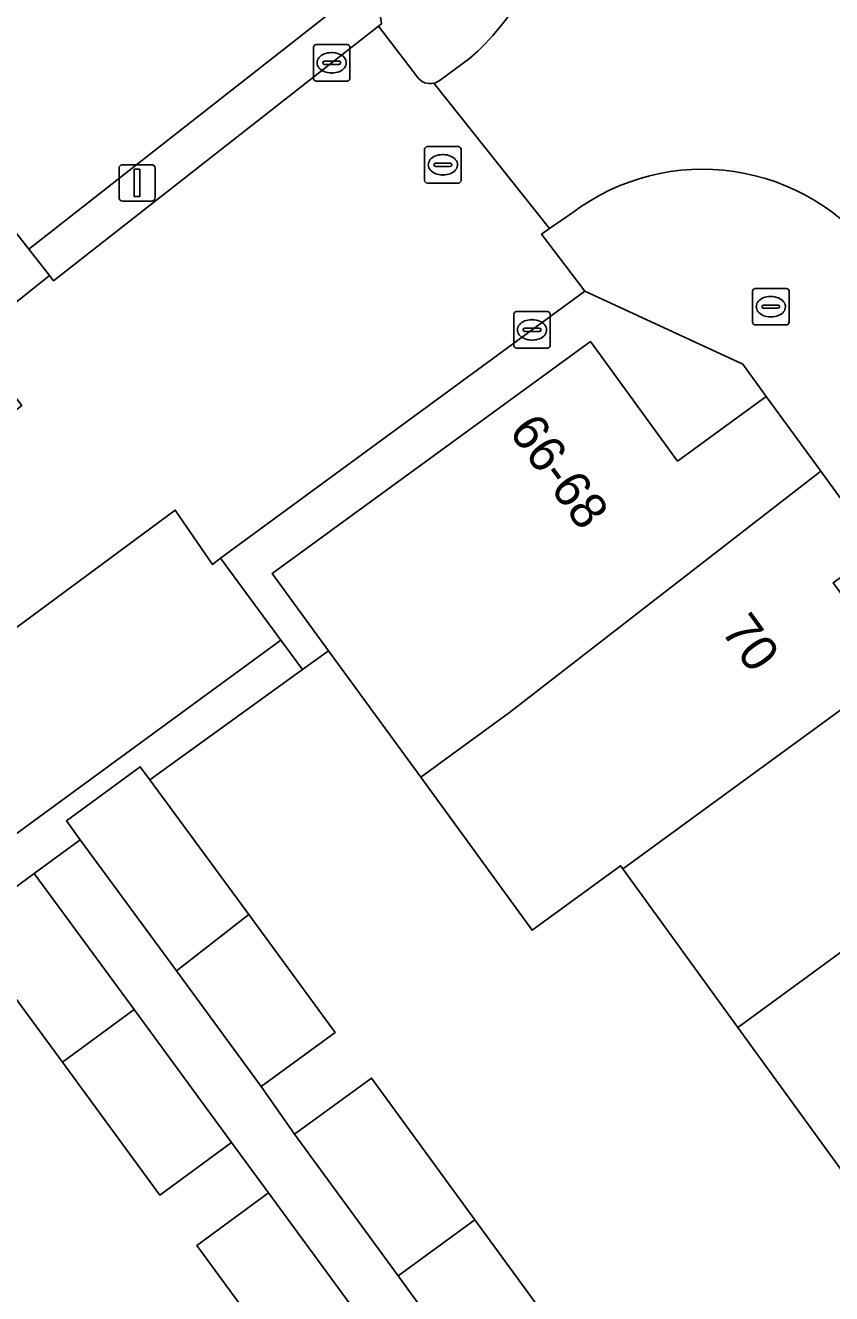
# Model space of a CAD drawing. Extents: x 160377 to 161131, y 383938 to 384853.
# Drawn here: x 160774.47 to 160796.6, y 384297.65 to 384332.45 of the extents above; entities that cross this region are included whole.
import ezdxf

# ---------------------------------------------------------------- set-up
doc = ezdxf.new("R2010")
doc.units = 0
for name, color, linetype in [('IMGEO_Brandkraan', 7, 'Continuous'), ('IMGEO_Erf', 7, 'Continuous'), ('IMGEO_Kolk', 7, 'Continuous'), ('IMGEO_Lichtmast', 7, 'Continuous'), ('IMGEO_Muur', 7, 'Continuous'), ('IMGEO_Pand', 7, 'Continuous'), ('IMGEO_Pand_nummerreeks', 7, 'Continuous'), ('IMGEO_Parkeervlak_open', 7, 'Continuous'), ('IMGEO_Rijbaan_lokaal_open', 7, 'Continuous'), ('IMGEO_Rioolput', 7, 'Continuous'), ('IMGEO_Voetpad_open', 7, 'Continuous')]:
    doc.layers.add(name, color=color, linetype=linetype)

msp = doc.modelspace()

# ---------------------------------------------------------------- linework, layer by layer
at = {"layer": 'IMGEO_Brandkraan'}
for p, q in [((160794.429, 384324.3), (160794.429, 384325.152)), ((160794.504, 384325.226), (160795.356, 384325.226)), ((160795.43, 384325.152), (160795.43, 384324.3)), ((160794.731, 384324.769), (160795.129, 384324.769)), ((160794.917, 384325.006), (160794.942, 384325.006)), ((160794.688, 384324.72), (160794.688, 384324.732)), ((160795.126, 384324.683), (160794.728, 384324.683)), ((160794.94, 384324.446), (160794.915, 384324.446)), ((160795.172, 384324.732), (160795.172, 384324.72)), ((160795.356, 384324.226), (160794.504, 384324.226))]:
    msp.add_line(p, q, dxfattribs=at)
for points in [[(160794.429, 384324.3), (160794.429, 384325.152)], [(160794.504, 384325.226), (160795.356, 384325.226)], [(160795.43, 384325.152), (160795.43, 384324.3)], [(160795.356, 384324.226), (160794.504, 384324.226)]]:
    msp.add_lwpolyline(points, dxfattribs=at)
for centre, radius, start, end in [((160794.506, 384325.15), 0.0765, 91.552, 178.448), ((160794.506, 384325.15), 0.0765, 91.552, 178.448), ((160795.354, 384325.15), 0.0765, 1.552, 88.448), ((160795.354, 384325.15), 0.0765, 1.552, 88.448), ((160794.728, 384324.729), 0.0403, 85.8775, 175.7526), ((160795.133, 384324.731), 0.0386, 1.7309, 96.639), ((160794.725, 384324.719), 0.0366, 178.938, 274.7102), ((160795.129, 384324.726), 0.043, 264.8664, 352.4533), ((160794.506, 384324.302), 0.0765, 181.552, 268.448), ((160794.506, 384324.302), 0.0765, 181.552, 268.448), ((160795.354, 384324.302), 0.0765, 271.552, 358.448), ((160795.354, 384324.302), 0.0765, 271.552, 358.448)]:
    msp.add_arc(centre, radius, start, end, dxfattribs=at)
for centre, major_axis, ratio, start_param, end_param in [((160794.916, 384324.726), (-0.387, 0.002), 0.722429, 4.712389, 7.853982), ((160794.941, 384324.726), (-0.39, 0.002), 0.717154, 1.570796, 4.712389)]:
    msp.add_ellipse(centre, major_axis=major_axis, ratio=ratio, start_param=start_param, end_param=end_param, dxfattribs=at)
at = {"layer": 'IMGEO_Erf'}
for points in [[(160784.161, 384332.424), (160784.24, 384332.486), (160783.548, 384337.293), (160782.871, 384338.156), (160780.522, 384336.316), (160783.117, 384333.004), (160774.566, 384326.307), (160775.131, 384325.585), (160775.244, 384325.441)], [(160781.247, 384317.41), (160789.979, 384323.771), (160792.369, 384320.491), (160794.806, 384322.267), (160794.159, 384323.148), (160789.826, 384325.15), (160779.821, 384317.833), (160781.485, 384315.578), (160782.079, 384314.774), (160782.792, 384315.29)]]:
    msp.add_lwpolyline(points, close=True, dxfattribs=at)
for points in [[(160797.184, 384300.607), (160794.027, 384304.956), (160790.871, 384309.304), (160790.808, 384309.391), (160788.379, 384307.622), (160785.321, 384311.819), (160782.792, 384315.29), (160782.079, 384314.774), (160777.889, 384311.744), (160780.6, 384308.05), (160782.97, 384304.821), (160780.944, 384303.335), (160781.86, 384302.027), (160783.971, 384303.568), (160786.807, 384299.682), (160789.387, 384296.147), (160787.276, 384294.606), (160788.245, 384293.386), (160790.217, 384294.857), (160793.111, 384290.977), (160795.57, 384287.68), (160793.597, 384286.209), (160794.747, 384284.594), (160796.653, 384285.998)], [(160781.693, 384295.545), (160779.177, 384298.972), (160781.143, 384300.415), (160780.127, 384301.799), (160778.161, 384300.357), (160775.484, 384304.001), (160773.157, 384307.171), (160764.092, 384300.584), (160766.451, 384297.369)]]:
    msp.add_lwpolyline(points, dxfattribs=at)
at = {"layer": 'IMGEO_Kolk'}
for p, q in [((160782.376, 384330.992), (160782.376, 384331.844)), ((160782.451, 384331.918), (160783.303, 384331.918)), ((160783.377, 384331.844), (160783.377, 384330.992)), ((160782.635, 384331.412), (160782.635, 384331.424)), ((160782.678, 384331.461), (160783.076, 384331.461)), ((160782.864, 384331.698), (160782.889, 384331.698)), ((160783.119, 384331.424), (160783.119, 384331.412)), ((160783.073, 384331.375), (160782.675, 384331.375)), ((160782.887, 384331.138), (160782.862, 384331.138)), ((160783.303, 384330.918), (160782.451, 384330.918)), ((160787.875, 384323.666), (160787.875, 384324.518)), ((160787.95, 384324.592), (160788.802, 384324.592)), ((160788.876, 384324.518), (160788.876, 384323.666)), ((160788.134, 384324.086), (160788.134, 384324.098)), ((160788.177, 384324.135), (160788.575, 384324.135)), ((160788.363, 384324.372), (160788.388, 384324.372)), ((160788.618, 384324.098), (160788.618, 384324.086)), ((160788.572, 384324.049), (160788.174, 384324.049)), ((160788.386, 384323.812), (160788.361, 384323.812)), ((160788.802, 384323.592), (160787.95, 384323.592))]:
    msp.add_line(p, q, dxfattribs=at)
for points in [[(160782.376, 384330.992), (160782.376, 384331.844)], [(160782.451, 384331.918), (160783.303, 384331.918)], [(160783.377, 384331.844), (160783.377, 384330.992)], [(160783.303, 384330.918), (160782.451, 384330.918)], [(160787.875, 384323.666), (160787.875, 384324.518)], [(160787.95, 384324.592), (160788.802, 384324.592)], [(160788.876, 384324.518), (160788.876, 384323.666)], [(160788.802, 384323.592), (160787.95, 384323.592)]]:
    msp.add_lwpolyline(points, dxfattribs=at)
for centre, radius, start, end in [((160782.453, 384331.842), 0.0765, 91.552, 178.448), ((160782.453, 384331.842), 0.0765, 91.552, 178.448), ((160783.301, 384331.842), 0.0765, 1.552, 88.448), ((160783.301, 384331.842), 0.0765, 1.552, 88.448), ((160782.675, 384331.421), 0.0403, 85.8775, 175.7526), ((160782.672, 384331.411), 0.0366, 178.938, 274.7102), ((160783.076, 384331.418), 0.043, 264.8664, 352.4533), ((160783.08, 384331.423), 0.0386, 1.7309, 96.639), ((160782.453, 384330.994), 0.0765, 181.552, 268.448), ((160782.453, 384330.994), 0.0765, 181.552, 268.448), ((160783.301, 384330.994), 0.0765, 271.552, 358.448), ((160783.301, 384330.994), 0.0765, 271.552, 358.448), ((160787.952, 384324.516), 0.0765, 91.552, 178.448), ((160787.952, 384324.516), 0.0765, 91.552, 178.448), ((160788.8, 384324.516), 0.0765, 1.552, 88.448), ((160788.8, 384324.516), 0.0765, 1.552, 88.448), ((160788.174, 384324.095), 0.0403, 85.8775, 175.7526), ((160788.171, 384324.085), 0.0366, 178.938, 274.7102), ((160788.575, 384324.092), 0.043, 264.8664, 352.4533), ((160788.579, 384324.097), 0.0386, 1.7309, 96.639), ((160787.952, 384323.668), 0.0765, 181.552, 268.448), ((160787.952, 384323.668), 0.0765, 181.552, 268.448), ((160788.8, 384323.668), 0.0765, 271.552, 358.448), ((160788.8, 384323.668), 0.0765, 271.552, 358.448)]:
    msp.add_arc(centre, radius, start, end, dxfattribs=at)
for centre, major_axis, ratio, start_param, end_param in [((160782.863, 384331.418), (-0.387, 0.002), 0.722429, 4.712389, 7.853982), ((160782.888, 384331.418), (-0.39, 0.002), 0.717154, 1.570796, 4.712389), ((160788.362, 384324.092), (-0.387, 0.002), 0.722429, 4.712389, 7.853982), ((160788.387, 384324.092), (-0.39, 0.002), 0.717154, 1.570796, 4.712389)]:
    msp.add_ellipse(centre, major_axis=major_axis, ratio=ratio, start_param=start_param, end_param=end_param, dxfattribs=at)
at = {"layer": 'IMGEO_Lichtmast'}
for p, q in [((160777.139, 384328.623), (160777.929, 384328.623)), ((160777.929, 384328.623), (160777.139, 384328.623)), ((160777.039, 384327.723), (160777.039, 384328.523)), ((160777.039, 384328.523), (160777.039, 384327.723)), ((160778.029, 384328.523), (160778.029, 384327.723)), ((160778.029, 384327.723), (160778.029, 384328.523)), ((160777.929, 384327.623), (160777.139, 384327.623)), ((160777.139, 384327.623), (160777.929, 384327.623))]:
    msp.add_line(p, q, dxfattribs=at)
msp.add_lwpolyline([(160777.459, 384328.498), (160777.609, 384328.498), (160777.609, 384327.748), (160777.459, 384327.748), (160777.459, 384328.498)], dxfattribs=at)
for centre, start, end in [((160777.139, 384328.523), 90, 180), ((160777.139, 384328.523), 90, 180), ((160777.929, 384328.523), 0, 90), ((160777.929, 384328.523), 360, 90), ((160777.139, 384327.723), 180, 270), ((160777.139, 384327.723), 180, 270), ((160777.929, 384327.723), 270, 0), ((160777.929, 384327.723), 270, 0)]:
    msp.add_arc(centre, 0.1, start, end, dxfattribs=at)
at = {"layer": 'IMGEO_Muur'}
for points in [[(160782.079, 384314.774), (160782.792, 384315.29)], [(160777.889, 384311.744), (160782.079, 384314.774)]]:
    msp.add_lwpolyline(points, dxfattribs=at)
at = {"layer": 'IMGEO_Pand'}
for points in [[(160780.522, 384336.316), (160782.871, 384338.156), (160781.263, 384340.208), (160772.644, 384333.455), (160770.365, 384331.67), (160772.875, 384328.466), (160774.566, 384326.307), (160783.117, 384333.004)], [(160796.302, 384320.213), (160794.806, 384322.267), (160792.369, 384320.491), (160789.979, 384323.771), (160781.247, 384317.41), (160782.792, 384315.29), (160785.321, 384311.819), (160787.757, 384313.594)], [(160798.376, 384314.787), (160796.645, 384317.157), (160797.875, 384318.053), (160796.302, 384320.213), (160787.757, 384313.594), (160785.321, 384311.819), (160788.379, 384307.622), (160790.808, 384309.391), (160790.871, 384309.304), (160790.959, 384309.368)], [(160794.027, 384304.956), (160794.125, 384305.027), (160801.545, 384310.447), (160798.376, 384314.787), (160790.959, 384309.368), (160790.871, 384309.304)], [(160778.613, 384306.511), (160780.6, 384308.05), (160777.889, 384311.744), (160777.622, 384312.108), (160775.596, 384310.622), (160775.975, 384310.105)], [(160794.027, 384304.956), (160797.184, 384300.607), (160797.291, 384300.685), (160804.715, 384306.108), (160801.545, 384310.447), (160794.125, 384305.027)], [(160774.715, 384309.175), (160772.747, 384307.73), (160773.157, 384307.171), (160775.484, 384304.001), (160777.452, 384305.445)], [(160778.613, 384306.511), (160780.944, 384303.335), (160782.97, 384304.821), (160780.6, 384308.05)], [(160777.452, 384305.445), (160775.484, 384304.001), (160778.161, 384300.357), (160780.127, 384301.799)], [(160784.697, 384298.14), (160786.807, 384299.682), (160783.971, 384303.568), (160781.86, 384302.027)], [(160781.143, 384300.415), (160779.177, 384298.972), (160781.693, 384295.545), (160783.658, 384296.988)], [(160784.697, 384298.14), (160787.276, 384294.606), (160789.387, 384296.147), (160786.807, 384299.682)]]:
    msp.add_lwpolyline(points, close=True, dxfattribs=at)
at = {"layer": 'IMGEO_Parkeervlak_open'}
msp.add_lwpolyline([(160761.293, 384306.371), (160763.903, 384302.735), (160781.485, 384315.578), (160779.821, 384317.833), (160779.604, 384317.657), (160778.583, 384319.147)], close=True, dxfattribs=at)
at = {"layer": 'IMGEO_Rijbaan_lokaal_open'}
for points in [[(160785.23, 384331.026), (160784.161, 384332.424), (160775.244, 384325.441), (160775.131, 384325.585), (160772.957, 384323.85), (160774.371, 384322.018), (160765.649, 384315.071), (160763.307, 384313.206), (160761.275, 384315.785), (160741.768, 384300.44), (160742.088, 384300.038), (160734.254, 384295.2)], [(160786.656, 384331.534), (160785.852, 384330.945)], [(160760.382, 384305.698), (160761.293, 384306.371), (160778.583, 384319.147), (160779.604, 384317.657), (160779.821, 384317.833), (160789.826, 384325.15), (160788.635, 384326.714), (160788.858, 384326.869), (160785.679, 384330.858)], [(160785.679, 384330.858), (160788.858, 384326.869), (160789.495, 384327.313)]]:
    msp.add_lwpolyline(points, dxfattribs=at)
for centre, radius, start, end in [((160782.686, 384336.248), 6.163, 310.1054, 36.8104), ((160785.578, 384331.271), 0.425, 215.1624, 283.8094), ((160785.59, 384331.25), 0.401, 282.74, 310.6548), ((160793.058, 384322.555), 5.944, 36.4417, 126.8293)]:
    msp.add_arc(centre, radius, start, end, dxfattribs=at)
at = {"layer": 'IMGEO_Rioolput'}
for p, q in [((160785.427, 384328.194), (160785.427, 384329.046)), ((160785.502, 384329.12), (160786.354, 384329.12)), ((160786.428, 384329.046), (160786.428, 384328.194)), ((160785.686, 384328.614), (160785.686, 384328.626)), ((160785.729, 384328.663), (160786.127, 384328.663)), ((160785.915, 384328.9), (160785.94, 384328.9)), ((160786.17, 384328.626), (160786.17, 384328.614)), ((160786.124, 384328.577), (160785.726, 384328.577)), ((160785.938, 384328.34), (160785.913, 384328.34)), ((160786.354, 384328.12), (160785.502, 384328.12))]:
    msp.add_line(p, q, dxfattribs=at)
for points in [[(160785.427, 384328.194), (160785.427, 384329.046)], [(160785.502, 384329.12), (160786.354, 384329.12)], [(160786.428, 384329.046), (160786.428, 384328.194)], [(160786.354, 384328.12), (160785.502, 384328.12)]]:
    msp.add_lwpolyline(points, dxfattribs=at)
for centre, radius, start, end in [((160785.504, 384329.044), 0.0765, 91.552, 178.448), ((160785.504, 384329.044), 0.0765, 91.552, 178.448), ((160786.352, 384329.044), 0.0765, 1.552, 88.448), ((160786.352, 384329.044), 0.0765, 1.552, 88.448), ((160785.726, 384328.623), 0.0403, 85.8775, 175.7526), ((160785.723, 384328.613), 0.0366, 178.938, 274.7102), ((160786.127, 384328.62), 0.043, 264.8664, 352.4533), ((160786.131, 384328.625), 0.0386, 1.7309, 96.639), ((160785.504, 384328.196), 0.0765, 181.552, 268.448), ((160785.504, 384328.196), 0.0765, 181.552, 268.448), ((160786.352, 384328.196), 0.0765, 271.552, 358.448), ((160786.352, 384328.196), 0.0765, 271.552, 358.448)]:
    msp.add_arc(centre, radius, start, end, dxfattribs=at)
for centre, major_axis, ratio, start_param, end_param in [((160785.914, 384328.62), (-0.387, 0.002), 0.722429, 4.712389, 7.853982), ((160785.939, 384328.62), (-0.39, 0.002), 0.717154, 1.570796, 4.712389)]:
    msp.add_ellipse(centre, major_axis=major_axis, ratio=ratio, start_param=start_param, end_param=end_param, dxfattribs=at)
at = {"layer": 'IMGEO_Voetpad_open'}
for points in [[(160741.838, 384390.167), (160745.545, 384385.618), (160746.222, 384384.753), (160747.817, 384382.717), (160749.411, 384380.682), (160759.699, 384367.649), (160761.277, 384365.634), (160762.855, 384363.62), (160779.656, 384342.26), (160781.263, 384340.208), (160782.871, 384338.156), (160783.548, 384337.293), (160784.24, 384332.486), (160784.161, 384332.424), (160785.23, 384331.026)], [(160785.852, 384330.945), (160786.656, 384331.534)], [(160772.957, 384323.85), (160775.131, 384325.585), (160774.566, 384326.307), (160772.875, 384328.466)], [(160789.495, 384327.313), (160788.858, 384326.869), (160788.635, 384326.714), (160789.826, 384325.15), (160794.159, 384323.148), (160794.806, 384322.267), (160796.302, 384320.213), (160797.875, 384318.053), (160813.914, 384295.859), (160815.337, 384293.904), (160816.815, 384291.874), (160818.185, 384289.971), (160818.589, 384289.25), (160819.896, 384286.919), (160823.993, 384279.608), (160825.21, 384277.471), (160826.528, 384275.156), (160834.746, 384260.75), (160835.921, 384258.686), (160837.308, 384256.252), (160837.8, 384255.489)], [(160797.493, 384280.868), (160794.747, 384284.594), (160793.597, 384286.209), (160791.124, 384289.526), (160788.245, 384293.386), (160787.276, 384294.606), (160784.697, 384298.14), (160781.86, 384302.027), (160780.944, 384303.335), (160778.613, 384306.511), (160775.975, 384310.105), (160774.715, 384309.175), (160777.452, 384305.445), (160780.127, 384301.799), (160781.143, 384300.415), (160783.658, 384296.988), (160786.488, 384293.133), (160787.562, 384291.669), (160790.219, 384288.047), (160792.878, 384284.425), (160793.386, 384283.733), (160793.939, 384282.98), (160796.553, 384279.417), (160797.659, 384277.91)]]:
    msp.add_lwpolyline(points, dxfattribs=at)
msp.add_lwpolyline([(160774.715, 384309.175), (160775.975, 384310.105), (160775.596, 384310.622), (160777.622, 384312.108), (160777.889, 384311.744), (160782.079, 384314.774), (160781.485, 384315.578), (160763.903, 384302.735), (160761.293, 384306.371), (160760.382, 384305.698), (160762.333, 384302.98), (160764.092, 384300.584), (160773.157, 384307.171), (160772.747, 384307.73)], close=True, dxfattribs=at)
for centre, radius, start, end in [((160782.686, 384336.248), 6.163, 310.1054, 36.8104), ((160785.578, 384331.271), 0.425, 215.1624, 283.8094), ((160785.59, 384331.25), 0.401, 282.74, 310.6548), ((160793.058, 384322.555), 5.944, 36.4417, 126.8293)]:
    msp.add_arc(centre, radius, start, end, dxfattribs=at)

# ---------------------------------------------------------------- texts
at = {"layer": 'IMGEO_Pand_nummerreeks'}
for s, rotation, p in [('66-68', 306.0793, (160787.717, 384321.305)), ('70', 305.9242, (160793.541, 384315.833))]:
    msp.add_text(s, height=1, rotation=rotation, dxfattribs=at).set_placement(p)

doc.saveas('drawing.dxf')
